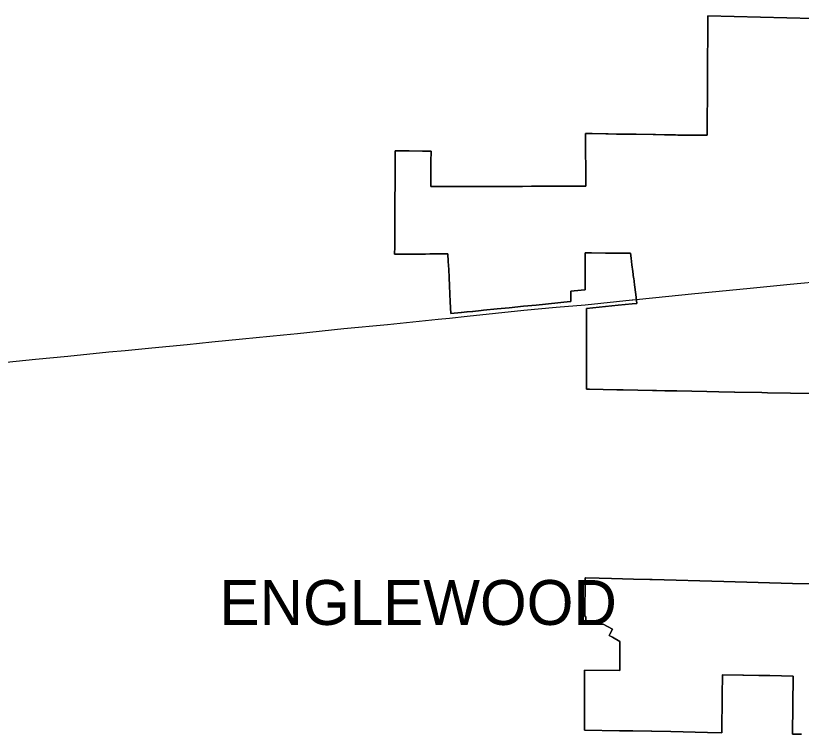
# Model space of a CAD drawing. Extents: x 0 to 34, y 0 to 22.
# Drawn here: x 4.5839 to 4.7244, y 15.7802 to 15.9088 of the extents above; entities that cross this region are included whole.
import ezdxf

# ---------------------------------------------------------------- set-up
doc = ezdxf.new("R2010")
doc.units = 0
for name, color, linetype in [('GM_X_Corporation', 7, 'Continuous'), ('GM_X_Corporation_Text', 7, 'Continuous'), ('GM_X_US_Route', 7, 'Continuous')]:
    doc.layers.add(name, color=color, linetype=linetype)

msp = doc.modelspace()

# ---------------------------------------------------------------- linework, layer by layer
at = {"layer": 'GM_X_Corporation'}
for points in [[(4.72627, 15.84118), (4.72242, 15.84126), (4.71836, 15.84133), (4.71729, 15.84136), (4.71248, 15.84145), (4.71244, 15.84145), (4.70965, 15.8415), (4.7075, 15.84155), (4.70209, 15.84165), (4.7006, 15.84168), (4.69998, 15.84169), (4.69851, 15.84172), (4.6984, 15.84172), (4.69778, 15.84173), (4.69251, 15.84184), (4.69136, 15.84186), (4.68651, 15.84195), (4.68597, 15.84196), (4.68597, 15.84386), (4.68597, 15.84423), (4.68597, 15.84434), (4.68597, 15.84477), (4.68597, 15.84478), (4.68597, 15.84639), (4.68598, 15.84647), (4.68598, 15.84914), (4.68598, 15.84983), (4.68599, 15.85284), (4.68599, 15.85586), (4.68599, 15.85626), (4.68599, 15.85642), (4.69164, 15.85699), (4.69412, 15.85724), (4.69499, 15.85732), (4.69478, 15.85892), (4.69455, 15.86066), (4.6944, 15.86185), (4.69439, 15.86192), (4.69424, 15.86306), (4.69408, 15.86425), (4.69393, 15.86544), (4.69381, 15.86631), (4.69371, 15.86631), (4.69289, 15.86632), (4.69278, 15.86632), (4.69169, 15.86633), (4.69157, 15.86633), (4.69091, 15.86633), (4.69006, 15.86634), (4.68995, 15.86634), (4.68966, 15.86634), (4.68934, 15.86634), (4.68688, 15.86636), (4.68666, 15.86636), (4.68574, 15.86638), (4.68573, 15.85978), (4.68501, 15.85971), (4.68317, 15.85952), (4.68317, 15.85791), (4.68316, 15.85767), (4.68305, 15.85766), (4.67695, 15.85704), (4.67471, 15.85682), (4.67469, 15.85681), (4.67213, 15.85655), (4.67, 15.85634), (4.66753, 15.85609), (4.66714, 15.85605), (4.66562, 15.8559), (4.66561, 15.8559), (4.66561, 15.8559), (4.6656, 15.85589), (4.66559, 15.85589), (4.66558, 15.85589), (4.66461, 15.85579), (4.66456, 15.85579), (4.66358, 15.85569), (4.66357, 15.85569), (4.66356, 15.85569), (4.66355, 15.85569), (4.66354, 15.85569), (4.66169, 15.8555), (4.66159, 15.85758), (4.66152, 15.85903), (4.66146, 15.86047), (4.66145, 15.8605), (4.66139, 15.86194), (4.66132, 15.86338), (4.66125, 15.86483), (4.66119, 15.86619), (4.66027, 15.86618), (4.65984, 15.86618), (4.65947, 15.86618), (4.65907, 15.86617), (4.65795, 15.86617), (4.65715, 15.86616), (4.65669, 15.86616), (4.6554, 15.86615), (4.65369, 15.86614), (4.65309, 15.86614), (4.65165, 15.86613), (4.65166, 15.86744), (4.65168, 15.86995), (4.65168, 15.87017), (4.65168, 15.8712), (4.6517, 15.87369), (4.65171, 15.87508), (4.65171, 15.87598), (4.65171, 15.87655), (4.65172, 15.87805), (4.65173, 15.87928), (4.65174, 15.88036), (4.65174, 15.8811), (4.65174, 15.88157), (4.65175, 15.88303), (4.65176, 15.88356), (4.65176, 15.88459), (4.65176, 15.88464), (4.65424, 15.88461), (4.65662, 15.88459), (4.65695, 15.88458), (4.65816, 15.88457), (4.65815, 15.88264), (4.65814, 15.88218), (4.65813, 15.88068), (4.65812, 15.87892), (4.65812, 15.87823), (4.65837, 15.87823), (4.66106, 15.87824), (4.6619, 15.87824), (4.66253, 15.87824), (4.66274, 15.87824), (4.66559, 15.87824), (4.66647, 15.87824), (4.66813, 15.87824), (4.66941, 15.87825), (4.67205, 15.87826), (4.67356, 15.87827), (4.67364, 15.87827), (4.6745, 15.87827), (4.67615, 15.87828), (4.67725, 15.87828), (4.6777, 15.87829), (4.67917, 15.87829), (4.68071, 15.8783), (4.68115, 15.8783), (4.68215, 15.8783), (4.68344, 15.8783), (4.68499, 15.87831), (4.68582, 15.87831), (4.6858, 15.88773), (4.6866, 15.88772), (4.68697, 15.88771), (4.68942, 15.88767), (4.68981, 15.88767), (4.69135, 15.88764), (4.69175, 15.88764), (4.69448, 15.88759), (4.69487, 15.88759), (4.69789, 15.88754), (4.69831, 15.88753), (4.69989, 15.8875), (4.7003, 15.8875), (4.7019, 15.88747), (4.70231, 15.88746), (4.70401, 15.88744), (4.70442, 15.88743), (4.70482, 15.88742), (4.70523, 15.88742), (4.70756, 15.88741), (4.70758, 15.89733), (4.70764, 15.90882), (4.72649, 15.90831)], [(4.72649, 15.90831), (4.70764, 15.90882), (4.70758, 15.89733), (4.70756, 15.88741), (4.70753, 15.88741), (4.70523, 15.88742), (4.70482, 15.88742), (4.70442, 15.88743), (4.70401, 15.88744), (4.70231, 15.88746), (4.7019, 15.88747), (4.7003, 15.8875), (4.69989, 15.8875), (4.69831, 15.88753), (4.69789, 15.88754), (4.69487, 15.88759), (4.69448, 15.88759), (4.69175, 15.88764), (4.69135, 15.88764), (4.68981, 15.88767), (4.68942, 15.88767), (4.68697, 15.88771), (4.6866, 15.88772), (4.6858, 15.88773), (4.68582, 15.87831), (4.68499, 15.87831), (4.68344, 15.8783), (4.68215, 15.8783), (4.68115, 15.8783), (4.68071, 15.8783), (4.67917, 15.87829), (4.6777, 15.87829), (4.67725, 15.87828), (4.67615, 15.87828), (4.6745, 15.87827), (4.67364, 15.87827), (4.67356, 15.87827), (4.67205, 15.87826), (4.66941, 15.87825), (4.66813, 15.87824), (4.66647, 15.87824), (4.66559, 15.87824), (4.66274, 15.87824), (4.66253, 15.87824), (4.6619, 15.87824), (4.66106, 15.87824), (4.65837, 15.87823), (4.65812, 15.87823), (4.65812, 15.87892), (4.65813, 15.88068), (4.65814, 15.88218), (4.65815, 15.88264), (4.65816, 15.88457), (4.65695, 15.88458), (4.65662, 15.88459), (4.65424, 15.88461), (4.65176, 15.88464), (4.65176, 15.88459), (4.65176, 15.88356), (4.65175, 15.88303), (4.65174, 15.88157), (4.65174, 15.8811), (4.65174, 15.88036), (4.65173, 15.87928), (4.65172, 15.87805), (4.65171, 15.87655), (4.65171, 15.87598), (4.65171, 15.87508), (4.6517, 15.87369), (4.65168, 15.8712), (4.65168, 15.87017), (4.65168, 15.86995), (4.65166, 15.86744), (4.65165, 15.86613), (4.65309, 15.86614), (4.65369, 15.86614), (4.6554, 15.86615), (4.65669, 15.86616), (4.65715, 15.86616), (4.65795, 15.86617), (4.65907, 15.86617), (4.65947, 15.86618), (4.65984, 15.86618), (4.66027, 15.86618), (4.66119, 15.86619), (4.66125, 15.86483), (4.66132, 15.86338), (4.66139, 15.86194), (4.66146, 15.86047), (4.66152, 15.85903), (4.66159, 15.85758), (4.66169, 15.8555), (4.66354, 15.85569), (4.66355, 15.85569), (4.66356, 15.85569), (4.66357, 15.85569), (4.66358, 15.85569), (4.66456, 15.85579), (4.66461, 15.85579), (4.66558, 15.85589), (4.66559, 15.85589), (4.6656, 15.85589), (4.66561, 15.8559), (4.66561, 15.8559), (4.66562, 15.8559), (4.66714, 15.85605), (4.66753, 15.85609), (4.67, 15.85634), (4.67213, 15.85655), (4.67469, 15.85681), (4.67471, 15.85682), (4.67695, 15.85704), (4.68305, 15.85766), (4.68316, 15.85767), (4.68317, 15.85791), (4.68317, 15.85952), (4.68501, 15.85971), (4.68573, 15.85978), (4.68574, 15.86638), (4.68666, 15.86636), (4.68688, 15.86636), (4.68934, 15.86634), (4.68966, 15.86634), (4.68995, 15.86634), (4.69006, 15.86634), (4.69091, 15.86633), (4.69157, 15.86633), (4.69169, 15.86633), (4.69278, 15.86632), (4.69289, 15.86632), (4.69371, 15.86631), (4.69381, 15.86631), (4.69393, 15.86544), (4.69408, 15.86425), (4.69424, 15.86306), (4.69439, 15.86192), (4.6944, 15.86185), (4.69455, 15.86066), (4.69478, 15.85892), (4.69499, 15.85732), (4.69412, 15.85724), (4.69164, 15.85699), (4.68599, 15.85642), (4.68599, 15.85626), (4.68599, 15.85586), (4.68599, 15.85284), (4.68598, 15.84983), (4.68598, 15.84914), (4.68598, 15.84647), (4.68597, 15.84639), (4.68597, 15.84477), (4.68597, 15.84434), (4.68597, 15.84423), (4.68597, 15.84386), (4.68597, 15.84196), (4.68651, 15.84195), (4.69136, 15.84186), (4.69251, 15.84184), (4.69778, 15.84173), (4.6984, 15.84172), (4.69851, 15.84172), (4.69998, 15.84169), (4.7006, 15.84168), (4.70209, 15.84165), (4.7075, 15.84155), (4.70965, 15.8415), (4.71244, 15.84145), (4.71248, 15.84145), (4.71729, 15.84136), (4.71836, 15.84133), (4.72242, 15.84126), (4.72627, 15.84118)], [(4.72443, 15.78021), (4.72316, 15.78024), (4.7229, 15.78024), (4.72278, 15.78025), (4.72291, 15.79064), (4.71873, 15.79072), (4.71867, 15.79072), (4.71683, 15.79076), (4.71677, 15.79076), (4.71402, 15.79081), (4.71395, 15.79081), (4.71035, 15.79088), (4.71028, 15.79088), (4.71023, 15.78715), (4.71015, 15.78048), (4.70761, 15.78052), (4.70106, 15.7807), (4.69764, 15.78075), (4.69758, 15.78075), (4.69427, 15.78081), (4.69187, 15.78085), (4.68562, 15.78095), (4.6856, 15.78245), (4.6856, 15.78309), (4.68561, 15.78605), (4.68561, 15.78686), (4.68562, 15.78902), (4.68562, 15.79088), (4.68563, 15.79167), (4.69192, 15.79165), (4.69193, 15.7934), (4.69194, 15.79683), (4.69061, 15.79757), (4.69002, 15.79789), (4.69, 15.7979), (4.69011, 15.7981), (4.69061, 15.799), (4.68894, 15.79992), (4.68582, 15.79994), (4.68582, 15.79994), (4.68582, 15.8012), (4.68582, 15.80131), (4.68569, 15.80131), (4.68571, 15.80824), (4.68577, 15.80824), (4.68823, 15.80817), (4.69041, 15.8081), (4.69438, 15.80799), (4.69728, 15.80791), (4.69771, 15.80789), (4.7105, 15.80756), (4.7228, 15.80722), (4.72892, 15.80705)], [(4.72892, 15.80705), (4.7228, 15.80722), (4.7105, 15.80756), (4.69771, 15.80789), (4.69728, 15.80791), (4.69438, 15.80799), (4.69041, 15.8081), (4.68823, 15.80817), (4.68577, 15.80824), (4.68571, 15.80824), (4.68569, 15.80131), (4.68582, 15.80131), (4.68582, 15.8012), (4.68582, 15.79994), (4.68894, 15.79992), (4.69061, 15.799), (4.69011, 15.7981), (4.69, 15.7979), (4.69002, 15.79789), (4.69061, 15.79757), (4.69194, 15.79683), (4.69193, 15.7934), (4.69192, 15.79165), (4.68563, 15.79167), (4.68562, 15.79088), (4.68562, 15.78902), (4.68561, 15.78686), (4.68561, 15.78605), (4.6856, 15.78309), (4.6856, 15.78245), (4.68561, 15.78095), (4.69187, 15.78085), (4.69427, 15.78081), (4.69758, 15.78075), (4.69764, 15.78075), (4.70106, 15.7807), (4.70761, 15.78052), (4.71015, 15.78048), (4.71023, 15.78715), (4.71028, 15.79088), (4.71035, 15.79088), (4.71395, 15.79081), (4.71402, 15.79081), (4.71677, 15.79076), (4.71683, 15.79076), (4.71867, 15.79072), (4.71873, 15.79072), (4.72291, 15.79064), (4.72278, 15.78025), (4.7229, 15.78024), (4.72316, 15.78024), (4.72443, 15.78021)]]:
    msp.add_lwpolyline(points, dxfattribs=at)
at = {"layer": 'GM_X_US_Route'}
msp.add_line((4.68573, 15.8571), (4.69414, 15.85796), dxfattribs=at)
for points in [[(4.69834, 15.85838), (4.70473, 15.85903), (4.71156, 15.8597), (4.71523, 15.86006), (4.7224, 15.86078), (4.72878, 15.86137), (4.73038, 15.86155)], [(4.69414, 15.85796), (4.69422, 15.85797), (4.69834, 15.85838)], [(4.66144, 15.85471), (4.66459, 15.85503), (4.67476, 15.8561), (4.68054, 15.85665), (4.68573, 15.8571)], [(4.63427, 15.85196), (4.64258, 15.85283), (4.65035, 15.85357), (4.65946, 15.85451), (4.66144, 15.85471)], [(4.51745, 15.84054), (4.52225, 15.84102), (4.53141, 15.84192), (4.53911, 15.84265), (4.54923, 15.84366), (4.55748, 15.84445), (4.56761, 15.84544), (4.57329, 15.84597), (4.58046, 15.84666), (4.58743, 15.84733), (4.59323, 15.84791), (4.60056, 15.84863), (4.60346, 15.84891), (4.6082, 15.84939), (4.61455, 15.84996), (4.61896, 15.85044), (4.62445, 15.85099), (4.63178, 15.8517), (4.63427, 15.85196)]]:
    msp.add_lwpolyline(points, dxfattribs=at)

# ---------------------------------------------------------------- texts
at = {"layer": 'GM_X_Corporation_Text'}
msp.add_text('ENGLEWOOD', height=0.008037, rotation=0, dxfattribs=at).set_placement((4.62033, 15.79978))

doc.saveas('drawing.dxf')
